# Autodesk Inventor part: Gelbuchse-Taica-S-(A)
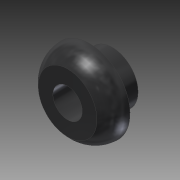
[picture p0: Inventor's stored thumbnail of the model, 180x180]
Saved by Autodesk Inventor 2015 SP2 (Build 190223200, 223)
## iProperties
Created: 2014-11
Part Number: Gelbuchse-Taica-S-(A)
Material: Gummi, Silikon
Document SubType Name: Modeling
Designer: Hübner
Density: 1.25 g/cm^3
Appearance: Gummi - schwarz - Version 1.1
Mass: 0.355717 g
Surface Area: 3.73915 cm^2
Volume: 0.284574 cm^3
Author: Hübner
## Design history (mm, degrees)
sketch "Skizze1"
  geometry: C1 r 3.5 at (0, 0); C2 r 5.5 at (0, 0); 1 further point
  constraints: 2 centre point, 2 coincident
  dimensions: "d0" = 7 diameter of C1; "d1" = 11 diameter of C2
extrude "Extrusion1" new body sketch "Skizze1" distance "d2" = 3.1; taper "d3" = 0 deg
extrude "Extrusion2" join sketch "Skizze1" distance "d4" = 3; taper "d5" = 0 deg
sketch "Skizze2"
  geometry: L1 (0, 5.5)-(-3, 5.5) reference; L2 (0, 5.5)-(0, -5.5) reference; L3 (-3, 5.5)-(-3, -5.5) reference; L4 (-3.812, 0)-(0.635, 0) reference; A1 r 3.75 centre (0, 1.75) between (0, 5.5) and (-3, 4); 1 further point
  constraints: 2 point on circle, 2 point on line, 1 centre point, 1 end point
  dimensions: "d20" = 4 distance from line of A1.end L4
revolve "Umdrehung1" sketch "Skizze2" stored, may be unused: angle "d17" = 90 deg
hole "Bohrung1" diameter "d8" = 4; stored, may be unused: countersink angle "d12" = 90 deg, drill point angle "d14" = 118 deg; dims "d9" = 6, "d10" = 4, "d11" = 2, "d13" = 8, "d21" = 10, "d22" = 10
node "Volumenkörper1"
